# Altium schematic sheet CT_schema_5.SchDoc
size 293 x 258 mm
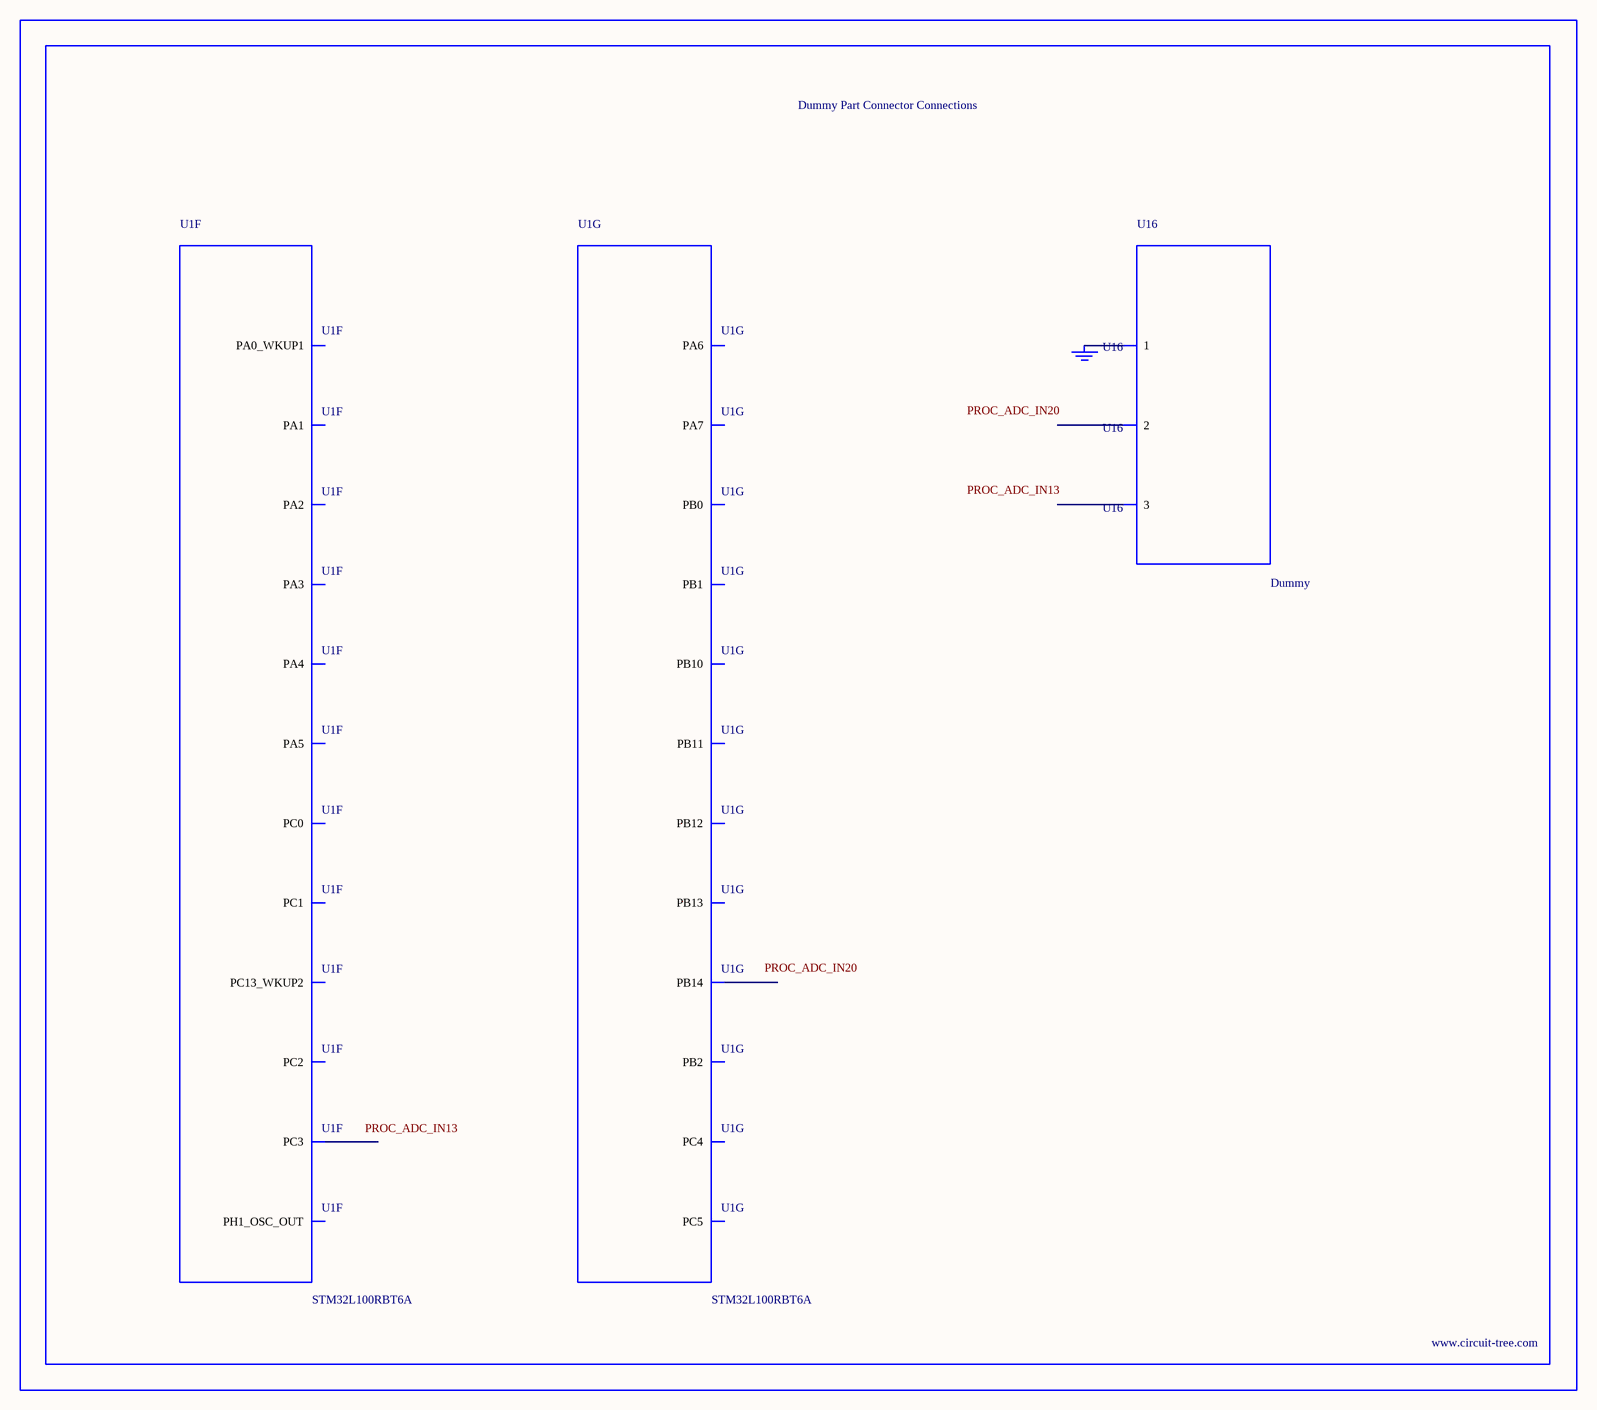
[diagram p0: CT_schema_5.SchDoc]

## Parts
BORDER4  (no value)
GND_INSTANCE_4_0  (no value)
U1  STM32L100RBT6A  [LQFP64]  (parts F,G of 7)
U16  Dummy  [DUMMY_PACKAGE_135]

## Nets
NetGND_INSTANCE_4_0_0: GND_INSTANCE_4_0.0(GND) U16.1

Not connected (* = marked no-connect by the designer): U1 2(PC13_WKUP2) 6(PH1_OSC_OUT) 8(PC0) 9(PC1) 10(PC2) 11(PC3) 14(PA0_WKUP1) 15(PA1) 16(PA2) 17(PA3) 20(PA4) 21(PA5) 22(PA6) 23(PA7) 24(PC4) 25(PC5) 26(PB0) 27(PB1) 28(PB2) 29(PB10) 30(PB11) 33(PB12) 34(PB13) 35(PB14); U16 2 3

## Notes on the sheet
- Labels drawn without touching a wire or pin: PROC_ADC_IN13, PROC_ADC_IN20

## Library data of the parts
BORDER4 = BORDER_PAGE4
GND_INSTANCE_4_0 = GND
